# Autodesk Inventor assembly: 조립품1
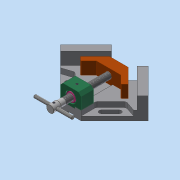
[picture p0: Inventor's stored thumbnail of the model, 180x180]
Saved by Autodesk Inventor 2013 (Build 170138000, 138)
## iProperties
Created: 2019-04
Part Number: 조립품1
Document SubType Name: Assembly
Designer: dgall
Author: dgall
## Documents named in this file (11)
- C:\Users\dgall\Desktop\490407V1013\조립품1.iam
- C:\Users\dgall\Desktop\490407V1013\리드스크류.ipt
- C:\Users\dgall\Desktop\490407V1013\멈춤나사 M4x5.ipt
- C:\Users\dgall\Desktop\490407V1013\멈춤나사 M4x10.ipt
- C:\Users\dgall\Desktop\490407V1013\본체.ipt
- C:\Users\dgall\Desktop\490407V1013\볼트 M4x16.ipt
- C:\Users\dgall\Desktop\490407V1013\부시.ipt
- C:\Users\dgall\Desktop\490407V1013\서포트.ipt
- C:\Users\dgall\Desktop\490407V1013\조.ipt
- C:\Users\dgall\Desktop\490407V1013\평행 핀 2.5x24.ipt
- C:\Users\dgall\Desktop\490407V1013\핸들.ipt
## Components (1 placed, 1 different names)
1. 핸들:1
